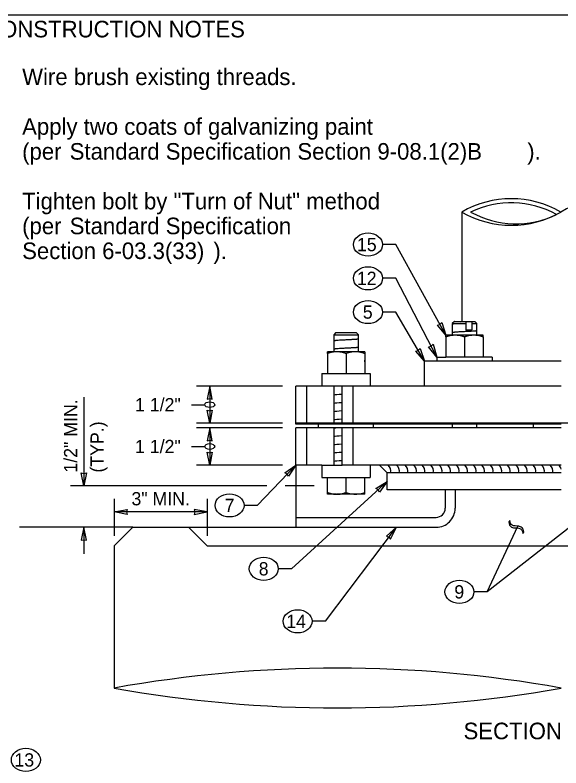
# Model space of a CAD drawing. Extents: x 99862 to 103151, y 100000 to 102076.
# Drawn here: x 100807 to 101466, y 101167 to 102076 of the extents above; entities that cross this region are included whole.
import ezdxf

# ---------------------------------------------------------------- set-up
doc = ezdxf.new("R2010")
doc.units = 0
for name, color, linetype in [('Level 1', 7, 'Continuous'), ('Level 12', 7, 'Continuous'), ('Level 15', 7, 'Continuous'), ('Level 2', 7, 'Continuous'), ('Level 20', 7, 'Continuous'), ('Level 3', 7, 'Continuous'), ('Level 4', 7, 'Continuous'), ('Level 6', 7, 'Continuous'), ('Level 62', 7, 'Continuous'), ('Level 7', 7, 'Continuous'), ('Level 9', 7, 'Continuous')]:
    doc.layers.add(name, color=color, linetype=linetype)

msp = doc.modelspace()

# ---------------------------------------------------------------- linework, layer by layer
at = {"layer": 'Level 1'}
msp.add_lwpolyline([(99862, 99999.5), (103151, 99999.5), (103151, 102075.5), (99862, 102075.5)], close=True, dxfattribs=at)
at = {"layer": 'Level 12'}
for p, q in [((100949.17, 101457.32), (100926.67, 101434.82)), ((100949.17, 101457.32), (101016.67, 101457.32)), ((101016.67, 101457.32), (101039.17, 101434.82)), ((100926.67, 101434.82), (100926.67, 101263.31)), ((101039.17, 101434.82), (101568.33, 101434.82))]:
    msp.add_line(p, q, dxfattribs=at)
for centre, start, end in [((101196.67, 99756.55), 79.84079, 100.15921), ((101196.67, 102770.06), 259.84079, 280.15921)]:
    msp.add_arc(centre, 1530.75, start, end, dxfattribs=at)
at = {"layer": 'Level 15'}
for p, q in [((101266.89, 101798.52), (101250.89, 101798.52)), ((101327.5, 101689.04), (101266.89, 101798.52)), ((101266.89, 101757.79), (101250.89, 101757.79)), ((101316.66, 101662.79), (101266.89, 101757.79)), ((101266.89, 101717.06), (101250.89, 101717.06)), ((101301.67, 101657.79), (101266.89, 101717.06)), ((101130.19, 101627.79), (101026.17, 101627.79)), ((101042.17, 101627.79), (101042.17, 101582.79)), ((100890.17, 101614.3), (100890.17, 101507.33)), ((101020.17, 101605.29), (101036.17, 101605.29)), ((101130.19, 101582.79), (101026.17, 101582.79)), ((101130.19, 101577.32), (101026.17, 101577.32)), ((101042.17, 101577.32), (101042.17, 101532.32)), ((101020.17, 101554.82), (101036.17, 101554.82)), ((101130.19, 101532.32), (101026.17, 101532.32)), ((101099.62, 101483.74), (101146.19, 101532.32)), ((101256.67, 101512.64), (101140.91, 101407.22)), ((101105.88, 101507.33), (100874.17, 101507.33)), ((101111.15, 101507.33), (101105.88, 101507.33)), ((101168.5, 101507.33), (101133.31, 101507.33)), ((101326.66, 101502.32), (101326.66, 101480.25)), ((101338.66, 101502.32), (101338.66, 101480.25)), ((100926.67, 101491.82), (100926.67, 101446.82)), ((101039.17, 101491.82), (101039.17, 101446.82)), ((101099.62, 101483.74), (101083.62, 101483.74)), ((101039.17, 101475.82), (100926.67, 101475.82)), ((101146.19, 101469.32), (101315.73, 101469.32)), ((101490.02, 101467.81), (101377.26, 101379.4)), ((100949.17, 101457.32), (100812.28, 101457.32)), ((100890.17, 101457.32), (100890.17, 101425.32)), ((101146.19, 101457.32), (101315.73, 101457.32)), ((101181.9, 101343.84), (101267.72, 101457.32)), ((101377.26, 101379.4), (101414.37, 101458.69)), ((101140.91, 101407.22), (101124.91, 101407.22)), ((101377.26, 101379.4), (101361.26, 101379.4)), ((101181.9, 101343.84), (101165.9, 101343.84))]:
    msp.add_line(p, q, dxfattribs=at)
for points in [[(101327.5, 101689.04), (101317.18, 101701.31), (101320.23, 101702.16), (101322.58, 101704.29)], [(101316.66, 101662.79), (101306.63, 101675.29), (101309.7, 101676.08), (101312.1, 101678.15)], [(101301.67, 101657.79), (101291.05, 101669.79), (101294.08, 101670.73), (101296.37, 101672.91)], [(101042.17, 101627.79), (101039.08, 101612.07), (101042.17, 101612.79), (101045.25, 101612.07)], [(101042.17, 101582.79), (101039.08, 101598.52), (101042.17, 101597.79), (101045.25, 101598.52)], [(101042.17, 101577.32), (101039.08, 101561.6), (101042.17, 101562.33), (101045.25, 101561.6)], [(101042.17, 101532.32), (101039.08, 101548.05), (101042.17, 101547.32), (101045.25, 101548.05)], [(101146.19, 101532.32), (101137.54, 101518.84), (101135.81, 101521.5), (101133.08, 101523.1)], [(100890.17, 101507.33), (100887.08, 101523.05), (100890.17, 101522.32), (100893.25, 101523.05)], [(101256.67, 101512.64), (101247.12, 101499.77), (101245.58, 101502.54), (101242.96, 101504.33)], [(100926.67, 101475.82), (100942.39, 101478.91), (100941.67, 101475.82), (100942.39, 101472.74)], [(101039.17, 101475.82), (101023.44, 101478.91), (101024.17, 101475.82), (101023.44, 101472.74)], [(100890.17, 101457.32), (100887.08, 101441.6), (100890.17, 101442.33), (100893.25, 101441.6)], [(101267.72, 101457.32), (101255.78, 101446.64), (101258.67, 101445.36), (101260.69, 101442.92)]]:
    msp.add_lwpolyline(points, close=True, dxfattribs=at)
for centre, radius, start, end in [((101406.46, 101734.24), 119.57, 60, 120), ((101406.46, 101734.24), 114.59, 61.53392, 115.35409), ((101526.42, 101734.5), 119.57, 59.74625, 120.23556), ((101406.46, 101941.35), 119.57, 240, 300), ((101411.92, 101935.23), 111.66, 240.76696, 296.12105), ((101315.73, 101480.25), 22.92, 269.99899, 0), ((101315.73, 101480.25), 10.92, 269.99899, 0)]:
    msp.add_arc(centre, radius, start, end, dxfattribs=at)
for centre in [(101042.17, 101605.29), (101042.17, 101554.82)]:
    msp.add_ellipse(centre, major_axis=(-6, 0), ratio=0.57735, dxfattribs=at)
at = {"layer": 'Level 2'}
for p, q in [((101146.24, 101581.85), (101146.24, 101582.79)), ((101215.52, 101582.79), (101146.24, 101582.79)), ((101466.67, 101581.85), (101146.24, 101581.85)), ((101494.53, 101582.79), (101215.52, 101582.79))]:
    msp.add_line(p, q, dxfattribs=at)
at = {"layer": 'Level 20'}
for p, q in [((101404.53, 101465.57), (101403.47, 101463.74)), ((101405.51, 101462), (101404.53, 101465.57)), ((101403.47, 101463.74), (101403.84, 101461.62)), ((101403.84, 101461.62), (101404.48, 101459.96)), ((101404.48, 101459.96), (101405.44, 101458.66)), ((101405.44, 101458.66), (101406.76, 101457.66)), ((101406.39, 101460.61), (101405.51, 101462)), ((101407.47, 101459.69), (101406.39, 101460.61)), ((101406.76, 101457.66), (101409.06, 101456.76)), ((101408.87, 101459.16), (101407.47, 101459.69)), ((101411.29, 101458.95), (101408.87, 101459.16)), ((101409.06, 101456.76), (101413.14, 101456.5)), ((101415.69, 101458.58), (101411.29, 101458.95)), ((101413.14, 101456.5), (101415.68, 101456.27)), ((101415.68, 101456.27), (101417.5, 101455.64)), ((101418.24, 101457.65), (101415.69, 101458.58)), ((101419.64, 101456.58), (101418.24, 101457.65)), ((101420.66, 101455.21), (101419.64, 101456.58)), ((101417.5, 101455.64), (101418.55, 101454.82)), ((101418.55, 101454.82), (101419.35, 101453.72)), ((101419.35, 101453.72), (101419.97, 101452.1)), ((101419.97, 101452.1), (101420.49, 101449.73)), ((101420.49, 101449.73), (101421.55, 101451.56)), ((101421.29, 101453.53), (101420.66, 101455.21)), ((101421.55, 101451.56), (101421.29, 101453.53))]:
    msp.add_line(p, q, dxfattribs=at)
for centre in [(101233.39, 101798.52), (101233.39, 101757.79), (101233.39, 101717.06), (101066.12, 101483.74), (101107.41, 101407.22), (101343.76, 101379.4), (101148.4, 101343.84), (100820.09, 101176.57)]:
    msp.add_ellipse(centre, major_axis=(-17.5, 0), ratio=0.8, dxfattribs=at)
at = {"layer": 'Level 3'}
for p, q in [((101146.19, 101582.79), (101146.19, 101627.79)), ((101159.64, 101627.79), (101146.19, 101627.79)), ((101159.64, 101582.79), (101159.64, 101627.79)), ((101177.53, 101627.79), (101159.64, 101627.79)), ((101236.19, 101627.79), (101177.53, 101627.79)), ((101202.12, 101582.79), (101202.12, 101627.79)), ((101215.52, 101582.79), (101215.52, 101627.79)), ((101301.67, 101627.79), (101236.19, 101627.79)), ((101466.67, 101627.79), (101301.67, 101627.79)), ((101146.24, 101582.79), (101146.19, 101582.79)), ((101159.64, 101582.79), (101146.19, 101582.79)), ((101215.52, 101582.79), (101202.12, 101582.79))]:
    msp.add_line(p, q, dxfattribs=at)
at = {"layer": 'Level 4'}
for p, q in [((101256.67, 101502.32), (101256.67, 101522.95)), ((101466.67, 101502.32), (101256.67, 101502.32))]:
    msp.add_line(p, q, dxfattribs=at)
at = {"layer": 'Level 6'}
for p in [(101146.19, 101532.32), (101016.67, 101457.32)]:
    msp.add_line(p, (101146.19, 101457.32), dxfattribs=at)
for centre, start in [((101251.6, 101525.08), 346.8528), ((101261.9, 101525.08), 346.8528), ((101272.2, 101525.08), 346.8528), ((101282.5, 101525.08), 346.8528), ((101292.8, 101525.08), 346.8528), ((101303.1, 101525.08), 346.8528), ((101313.4, 101525.08), 346.8528), ((101323.71, 101525.08), 346.8528), ((101334.01, 101525.08), 346.8528), ((101344.31, 101525.08), 346.8528), ((101354.61, 101525.08), 346.8528), ((101364.91, 101525.08), 346.8528), ((101375.21, 101525.08), 346.8528), ((101385.51, 101525.08), 346.8528), ((101395.81, 101525.08), 346.8528), ((101406.11, 101525.08), 346.8528), ((101416.41, 101525.08), 346.8528), ((101426.71, 101525.08), 346.8528), ((101437.01, 101525.08), 346.8528), ((101447.31, 101525.08), 346.8528), ((101457.61, 101525.08), 15.43114)]:
    msp.add_arc(centre, 9.4, start, 50.38098, dxfattribs=at)
at = {"layer": 'Level 62'}
for points, degree in [([(101345.65, 101703.13), (101340.09, 101702.79), (101336.48, 101702.51), (101335.37, 101702.26)], 3), ([(101335.03, 101699.27), (101334.92, 101699.22), (101334.92, 101699.16), (101335.03, 101699.1)], 3), ([(101335.03, 101694.27), (101334.93, 101694.22), (101334.93, 101694.16), (101335.03, 101694.1)], 3), ([(101364.62, 101694.39), (101363.77, 101694.18), (101361.77, 101694.01), (101359.1, 101693.87), (101349.48, 101693.34), (101337.95, 101692.84), (101335.37, 101692.25)], 4), ([(101221.54, 101684.4), (101220.69, 101684.19), (101218.69, 101684.03), (101216.03, 101683.89), (101206.41, 101683.35), (101194.88, 101682.85), (101192.29, 101682.26)], 4), ([(101335.03, 101689.26), (101334.93, 101689.21), (101334.93, 101689.15), (101335.03, 101689.09)], 3), ([(101221.54, 101674.39), (101220.69, 101674.18), (101218.69, 101674.01), (101216.03, 101673.87), (101206.41, 101673.34), (101194.88, 101672.84), (101192.29, 101672.25)], 4), ([(101202.12, 101617.7), (101196.79, 101617.37), (101193.37, 101617.1), (101192.29, 101616.86)], 3), ([(101202.12, 101607.69), (101196.8, 101607.36), (101193.39, 101607.08), (101192.29, 101606.85)], 3), ([(101202.12, 101597.67), (101196.8, 101597.35), (101193.36, 101597.07), (101192.29, 101596.83)], 3), ([(101202.12, 101587.66), (101196.83, 101587.34), (101193.38, 101587.06), (101192.29, 101586.82)], 3), ([(101197.23, 101577.32), (101194.61, 101577.12), (101192.96, 101576.95), (101192.29, 101576.81)], 3), ([(101335.03, 101579.22), (101334.94, 101579.17), (101334.94, 101579.11), (101335.03, 101579.06)], 3), ([(101202.12, 101567.65), (101196.79, 101567.33), (101193.37, 101567.06), (101192.29, 101566.82)], 3), ([(101202.12, 101557.65), (101196.8, 101557.32), (101193.39, 101557.04), (101192.29, 101556.81)], 3), ([(101202.12, 101547.63), (101196.8, 101547.31), (101193.36, 101547.03), (101192.29, 101546.79)], 3), ([(101202.12, 101537.63), (101196.79, 101537.3), (101193.37, 101537.03), (101192.29, 101536.78)], 3)]:
    msp.add_open_spline(points, degree=degree, dxfattribs=at)
at = {"layer": 'Level 7'}
for p, q in [((101146.19, 101532.32), (101146.19, 101577.32)), ((101173.53, 101577.32), (101146.19, 101577.32)), ((101159.64, 101532.32), (101159.64, 101577.32)), ((101202.12, 101577.32), (101173.53, 101577.32)), ((101202.12, 101532.32), (101202.12, 101577.32)), ((101215.52, 101577.32), (101202.12, 101577.32)), ((101215.52, 101532.32), (101215.52, 101577.32)), ((101466.67, 101577.32), (101215.52, 101577.32)), ((101177.53, 101532.32), (101146.19, 101532.32)), ((101215.52, 101532.32), (101202.12, 101532.32)), ((101236.19, 101532.32), (101215.52, 101532.32)), ((101247.29, 101532.32), (101236.19, 101532.32)), ((101466.67, 101532.32), (101247.29, 101532.32)), ((101247.29, 101532.32), (101256.67, 101522.95)), ((101466.67, 101522.95), (101256.67, 101522.95))]:
    msp.add_line(p, q, dxfattribs=at)
at = {"layer": 'Level 9'}
for p, q in [((101346.67, 101837.79), (101346.67, 101705.78)), ((101335.03, 101703.13), (101335.01, 101703.13)), ((101337.68, 101705.78), (101335.03, 101703.13)), ((101335.03, 101703.13), (101335.03, 101689.04)), ((101335.03, 101703.13), (101351.42, 101703.13)), ((101337.68, 101705.78), (101337.66, 101705.78)), ((101337.68, 101705.78), (101346.67, 101705.78)), ((101346.67, 101705.78), (101362.38, 101705.78)), ((101351.42, 101705.78), (101351.42, 101695.63)), ((101358.92, 101705.78), (101358.92, 101695.63)), ((101358.92, 101703.13), (101365.03, 101703.13)), ((101365.03, 101703.13), (101362.38, 101705.78)), ((101365.03, 101689.04), (101365.03, 101703.13)), ((101194.57, 101692.32), (101191.92, 101689.67)), ((101194.57, 101692.32), (101219.26, 101692.32)), ((101221.92, 101689.67), (101219.26, 101692.32)), ((101351.42, 101695.63), (101358.92, 101695.63)), ((101191.92, 101689.67), (101191.92, 101669.04)), ((101191.92, 101689.67), (101221.92, 101689.67)), ((101221.92, 101669.04), (101221.92, 101689.67)), ((101335.03, 101689.04), (101327.5, 101689.04)), ((101327.5, 101687.04), (101327.5, 101662.79)), ((101360.84, 101689.04), (101335.03, 101689.04)), ((101339.28, 101689.04), (101338.22, 101689.04)), ((101350, 101687.04), (101350, 101662.79)), ((101361.65, 101689.04), (101360.84, 101689.04)), ((101372.5, 101689.04), (101361.65, 101689.04)), ((101372.5, 101687.03), (101372.5, 101662.79)), ((101195.08, 101669.04), (101184.37, 101669.04)), ((101184.37, 101667.04), (101184.37, 101642.79)), ((101196.15, 101669.04), (101195.08, 101669.04)), ((101221.92, 101669.04), (101196.15, 101669.04)), ((101206.86, 101667.04), (101206.86, 101642.79)), ((101218.52, 101669.04), (101217.7, 101669.04)), ((101229.36, 101669.04), (101221.92, 101669.04)), ((101229.36, 101669.04), (101229.36, 101642.79)), ((101301.67, 101627.79), (101301.67, 101657.79)), ((101316.66, 101657.79), (101301.67, 101657.79)), ((101316.66, 101662.79), (101316.66, 101657.79)), ((101316.66, 101662.79), (101327.5, 101662.79)), ((101383.33, 101657.79), (101316.66, 101657.79)), ((101383.33, 101662.79), (101327.5, 101662.79)), ((101383.33, 101662.79), (101383.33, 101657.79)), ((101466.67, 101657.79), (101383.33, 101657.79)), ((101177.53, 101642.79), (101177.53, 101627.79)), ((101177.53, 101642.79), (101184.37, 101642.79)), ((101184.37, 101642.79), (101229.36, 101642.79)), ((101229.36, 101642.79), (101236.19, 101642.79)), ((101236.19, 101642.79), (101236.19, 101627.79)), ((101191.92, 101627.79), (101191.92, 101582.79)), ((101173.53, 101577.32), (101173.53, 101581.85)), ((101191.92, 101577.32), (101191.92, 101532.32)), ((101240.19, 101577.32), (101240.19, 101581.85)), ((101335.03, 101581.85), (101335.03, 101577.32)), ((101365.03, 101577.32), (101365.03, 101581.85)), ((101433.33, 101577.32), (101433.33, 101581.85)), ((101177.53, 101532.32), (101177.53, 101517.32)), ((101177.53, 101532.32), (101191.92, 101532.32)), ((101191.92, 101532.32), (101202.12, 101532.32)), ((101236.19, 101532.32), (101236.19, 101517.32)), ((101177.53, 101517.32), (101184.5, 101517.32)), ((101184.5, 101499.33), (101184.5, 101517.32)), ((101184.5, 101517.32), (101229.49, 101517.32)), ((101207, 101499.34), (101207, 101517.32)), ((101229.49, 101499.34), (101229.49, 101517.32)), ((101229.49, 101517.32), (101236.19, 101517.32)), ((101195.49, 101497.33), (101184.5, 101497.33)), ((101195.49, 101497.33), (101196, 101497.33)), ((101229.49, 101497.33), (101196, 101497.33))]:
    msp.add_line(p, q, dxfattribs=at)
for points, degree in [([(101327.5, 101687.04), (101327.5, 101688.21), (101327.5, 101688.98), (101327.5, 101689.04)], 2), ([(101338.22, 101689.04), (101334.57, 101688.98), (101331, 101688.2), (101327.5, 101687.04)], 2), ([(101350, 101687.04), (101346.49, 101688.21), (101342.93, 101688.98), (101339.28, 101689.04)], 2), ([(101360.84, 101689.04), (101357.15, 101688.99), (101353.54, 101688.22), (101350, 101687.04)], 2), ([(101372.5, 101687.03), (101368.94, 101688.22), (101365.34, 101688.99), (101361.65, 101689.04)], 2), ([(101372.5, 101687.03), (101372.5, 101688.25), (101372.5, 101689.04), (101372.5, 101689.04)], 2), ([(101184.37, 101667.04), (101184.37, 101668.21), (101184.37, 101668.98), (101184.37, 101669.04)], 2), ([(101195.08, 101669.04), (101191.43, 101668.98), (101187.87, 101668.2), (101184.37, 101667.04)], 2), ([(101206.86, 101667.04), (101203.35, 101668.21), (101199.79, 101668.98), (101196.15, 101669.04)], 2), ([(101217.7, 101669.04), (101214.01, 101668.99), (101210.4, 101668.22), (101206.86, 101667.04)], 2), ([(101229.36, 101667.03), (101225.81, 101668.22), (101222.21, 101668.99), (101218.52, 101669.04)], 2), ([(101229.36, 101657.03), (101229.36, 101658.25), (101229.36, 101659.04), (101229.36, 101659.04)], 2), ([(101229.36, 101659.04), (101229.36, 101659.04), (101229.36, 101659.04), (101229.36, 101659.04)], 2), ([(101184.5, 101497.33), (101184.5, 101497.39), (101184.5, 101498.17), (101184.5, 101499.33)], 2), ([(101184.5, 101499.33), (101188.09, 101498.13), (101191.74, 101497.36), (101195.49, 101497.33)], 2), ([(101196, 101497.33), (101199.74, 101497.36), (101203.41, 101498.14), (101207, 101499.34)], 2), ([(101207, 101499.34), (101210.67, 101498.11), (101214.4, 101497.33), (101222.05, 101497.32), (101225.81, 101498.11), (101229.49, 101499.34)], 3), ([(101229.49, 101497.33), (101229.49, 101497.33), (101229.49, 101498.12), (101229.49, 101499.34)], 2), ([(101229.49, 101497.33), (101229.49, 101497.33), (101229.49, 101497.33), (101229.49, 101497.33)], 2)]:
    msp.add_open_spline(points, degree=degree, dxfattribs=at)

# ---------------------------------------------------------------- texts
at = {"layer": 'Level 20'}
for s, height, p in [('CONSTRUCTION NOTES', 20, (100769.71, 102048.54)), ('Wire brush existing threads.', 20, (100815.62, 101991)), ('Apply two coats of galvanizing paint ', 20, (100815.62, 101931)), ('(per ', 20, (100815.62, 101901)), ('Standard Specification Section 9-08.1(2)B', 20, (100873.05, 101901)), (').', 20, (101425.71, 101901)), ('Tighten bolt by "Turn of Nut" method', 20, (100815.62, 101841)), ('(per ', 20, (100815.62, 101811)), ('Standard Specification ', 20, (100873.05, 101811)), ('Section 6-03.3(33)', 20, (100815.62, 101781)), (').', 20, (101046.63, 101781)), ('15', 16, (101220.01, 101790.52)), ('12', 16, (101219.95, 101749.79)), ('5', 16, (101227.08, 101709.06)), ('7', 16, (101060.18, 101475.74)), ('8', 16, (101101.39, 101399.23)), ('9', 16, (101337.67, 101371.4)), ('14', 16, (101134.62, 101335.84)), ('SECTION', 20, (101348.74, 101201.53)), ('13', 16, (100806.32, 101168.57))]:
    msp.add_text(s, height=height, dxfattribs=at).set_placement(p)
for s, rotation, p in [('1 1/2"', 360, (100951.99, 101597.29)), ('1/2" MIN.', 90, (100882.17, 101523.33)), ('(TYP.)', 90, (100914.17, 101523.33)), ('1 1/2"', 360, (100951.99, 101546.82)), ('3" MIN.', 360, (100947.67, 101483.82))]:
    msp.add_text(s, height=16, rotation=rotation, dxfattribs=at).set_placement(p)

doc.saveas('drawing.dxf')
